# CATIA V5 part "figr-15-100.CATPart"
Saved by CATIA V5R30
Part number: Part1
Bounding box of the stored display mesh (mm): x -52.43 to 60.529, y -25.631 to 32.893, z 0 to 4
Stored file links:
  D:\PROJECTS\CATIA V56R 2020\Resources\Parts File\c15_catia_v5_6r2020_prt\figr-15-100.CATPart
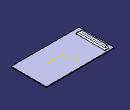
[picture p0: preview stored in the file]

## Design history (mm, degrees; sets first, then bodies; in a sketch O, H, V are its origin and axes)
SheetMetalParameters1: Thickness 1, BendRadius 5, KFactor 0.5 {= log(min(100,max(20*SheetMetalParameters1.BendRadius,SheetMetalParameters1.Thickness)/SheetMetalParameters1.Thickness))/log(100)/2}, ReliefRadialLength 1, ReliefAxialLength 2, MinimumBendRadius 0
Body1 (main body)
  Sketch1 on xy-plane, origin (0, 0, 0), H (1, 0, 0), V (0, 1, 0)
    line L1 (-52.4297, 32.8934) -> (60.5286, 32.8934)
    line L2 (60.5286, 32.8934) -> (60.5286, -25.6312)
    line L3 (60.5286, -25.6312) -> (-52.4297, -25.6312)
    line L4 (-52.4297, -25.6312) -> (-52.4297, 32.8934)
    horizontal: L1 H, L3 H
    vertical: L2 V, L4 V
  Wall1: Thickness 1, Profile Sketch1
  Sketch2 on face of Wall1, origin (0, 0, 1), H (1, 0, 0), V (0, 1, 0)
    line L1 (-47.3159, -16.5837) -> (-43.073, -16.5837)
    line L2 (-43.073, -16.5837) -> (-43.073, 26.788)
    line L3 (-43.073, 26.788) -> (-47.3159, 26.788)
    line L4 (-47.3159, 26.788) -> (-47.3159, -16.5837)
    horizontal: L1 H, L3 H
    vertical: L2 V, L4 V
  d_Stamp1: Stamp_FilletRadius 2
